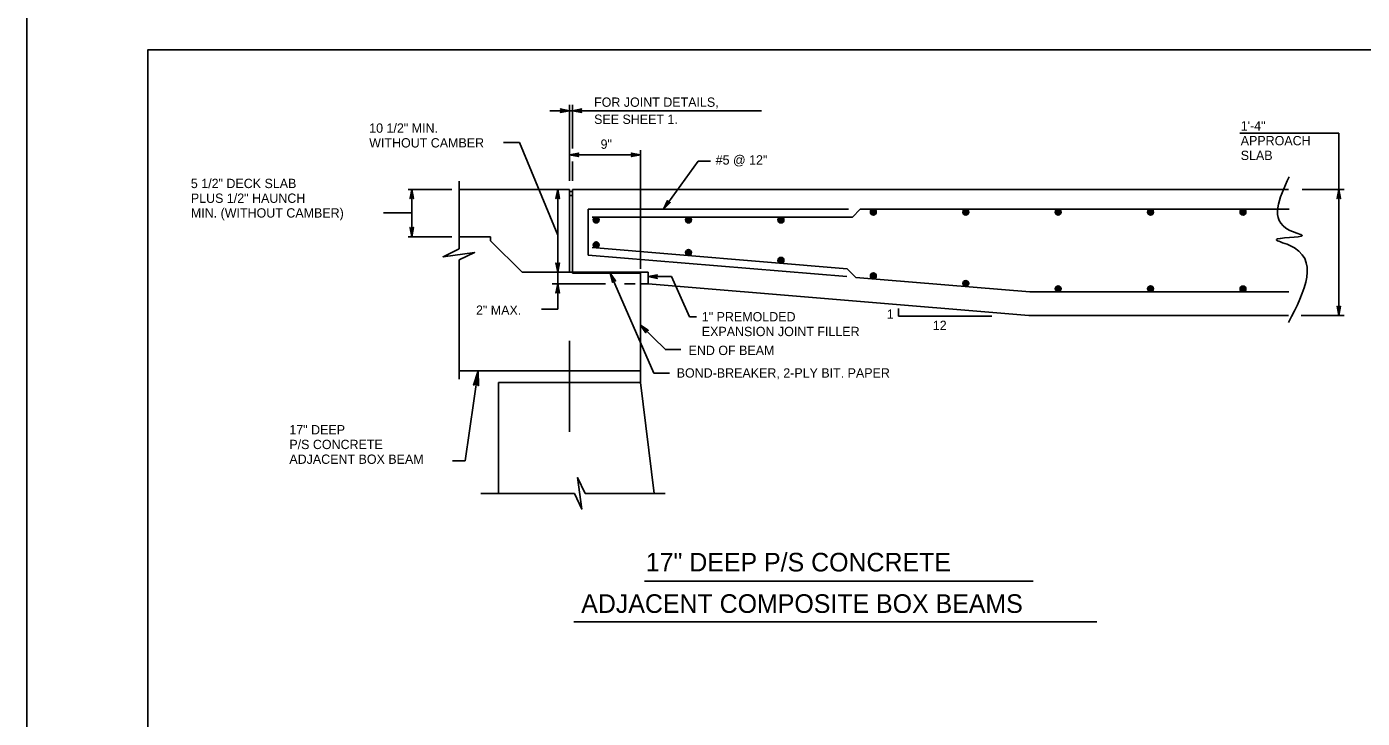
# Model space of a CAD drawing. Extents: x 638079 to 640019, y 297691 to 298879.
# Drawn here: x 638274 to 638704.2, y 298055 to 298277.7 of the extents above; entities that cross this region are included whole.
import ezdxf

# ---------------------------------------------------------------- set-up
doc = ezdxf.new("R2010")
doc.units = 0
doc.layers.add('1', color=7, linetype='Continuous')
doc.layers.add('PLT-BNDY', color=7, linetype='Continuous')

msp = doc.modelspace()

# ---------------------------------------------------------------- linework, layer by layer
at = {"layer": '1'}
for p, q in [((638442.52, 298250.68), (638510.73, 298250.68)), ((638448.85, 298228.12), (638448.85, 298252.54)), ((638449.8, 298238.5), (638449.8, 298252.54)), ((638664.75, 298243.41), (638696.63, 298243.41)), ((638696.63, 298184.69), (638696.63, 298243.41)), ((638471.71, 298236.45), (638448.85, 298236.45)), ((638471.71, 298199.8), (638471.71, 298237.97)), ((638449.8, 298228.12), (638449.8, 298234.3)), ((638490.27, 298234.45), (638479.1, 298218.98)), ((638490.27, 298234.45), (638494.22, 298234.45)), ((638413.31, 298227.96), (638413.31, 298206.16)), ((638396.92, 298225.33), (638410.98, 298225.33)), ((638398.04, 298210.09), (638398.04, 298225.33)), ((638413.31, 298225.33), (638448.85, 298225.33)), ((638447.1, 298225.33), (638443.31, 298225.33)), ((638445.06, 298186.72), (638445.06, 298225.33)), ((638448.85, 298225.33), (638448.85, 298198.66)), ((638448.85, 298223.42), (638449.8, 298223.42)), ((638449.8, 298225.33), (638680.46, 298225.33)), ((638449.8, 298225.33), (638449.8, 298198.66)), ((638684.79, 298225.33), (638698.38, 298225.33)), ((638454.88, 298218.98), (638454.88, 298204.17)), ((638454.88, 298218.98), (638538.7, 298218.98)), ((638539.97, 298216.44), (638542.51, 298218.98)), ((638542.51, 298218.98), (638680.64, 298218.98)), ((638388.91, 298217.81), (638398.04, 298217.81)), ((638456.1, 298216.44), (638539.97, 298216.44)), ((638396.92, 298210.09), (638410.98, 298210.09)), ((638413.31, 298210.09), (638423.44, 298210.09)), ((638423.44, 298208.82), (638423.44, 298210.09)), ((638433.61, 298198.66), (638423.44, 298208.82)), ((638456.1, 298206.62), (638538.33, 298199.76)), ((638413.31, 298202.64), (638413.31, 298164.25)), ((638454.88, 298204.17), (638538.12, 298197.23)), ((638433.61, 298198.66), (638471.71, 298198.66)), ((638449.8, 298198.36), (638449.8, 298198.66)), ((638449.8, 298198.36), (638449.8, 298198.66)), ((638449.8, 298198.36), (638471.71, 298198.36)), ((638453.1, 298198.66), (638467.52, 298198.66)), ((638471.71, 298198.66), (638471.71, 298163.1)), ((638474.21, 298197.23), (638481.68, 298197.23)), ((638481.68, 298197.23), (638487.45, 298184.28)), ((638538.33, 298199.76), (638541.11, 298196.98)), ((638460.48, 298194.91), (638443.31, 298194.91)), ((638469.96, 298194.91), (638466.53, 298194.91)), ((638474.21, 298194.91), (638596.83, 298184.69)), ((638541.11, 298196.98), (638597.15, 298192.31)), ((638597.15, 298192.31), (638680.53, 298192.31)), ((638596.83, 298184.69), (638680.46, 298184.69)), ((638684.47, 298184.69), (638698.38, 298184.69)), ((638489.71, 298184.28), (638487.45, 298184.28)), ((638448.85, 298147.27), (638448.85, 298176.57)), ((638471.71, 298166.91), (638413.31, 298166.91)), ((638415.28, 298137.88), (638419.42, 298166.91)), ((638425.99, 298163.1), (638471.71, 298163.1)), ((638425.99, 298127.36), (638425.99, 298163.1)), ((638476.17, 298127.36), (638471.71, 298163.1)), ((638411.14, 298137.88), (638415.28, 298137.88)), ((638450.42, 298127.36), (638420.24, 298127.36)), ((638479.61, 298127.36), (638453.94, 298127.36)), ((638473.01, 298099.18), (638598.21, 298099.18)), ((638450.27, 298086.05), (638618.7, 298086.05))]:
    msp.add_line(p, q, dxfattribs=at)
for points in [[(639099.03, 297706.23), (639099.03, 298270.23), (638313.03, 298270.23), (638313.03, 297706.23), (639099.03, 297706.23), (639099.03, 297732.59), (638899.03, 297732.59), (638899.03, 297797.26), (639099.03, 297797.26), (639099.03, 297826.23), (638899.03, 297826.23), (638899.03, 297706.23), (638977.83, 297706.23), (638977.83, 297732.59), (638977.83, 297706.23), (639054.83, 297706.23), (639054.83, 297732.59), (639054.83, 297720.27), (639099.03, 297720.27)], [(638448.85, 298250.68), (638445.86, 298250.12), (638445.98, 298250.2), (638446.09, 298250.28), (638446.15, 298250.38), (638446.21, 298250.48), (638446.23, 298250.58), (638446.25, 298250.68), (638446.23, 298250.78), (638446.21, 298250.88), (638446.15, 298250.98), (638446.09, 298251.08), (638445.98, 298251.16), (638445.86, 298251.24), (638448.85, 298250.68), (638445.98, 298251.16), (638446.09, 298251.08), (638448.85, 298250.68), (638446.15, 298250.98), (638446.21, 298250.88), (638448.85, 298250.68), (638446.23, 298250.78), (638446.25, 298250.68), (638448.85, 298250.68), (638446.23, 298250.58), (638446.21, 298250.48), (638448.85, 298250.68), (638446.15, 298250.38), (638446.09, 298250.28), (638448.85, 298250.68), (638445.98, 298250.2)], [(638449.8, 298250.68), (638452.78, 298251.24), (638452.67, 298251.16), (638452.55, 298251.08), (638452.49, 298250.98), (638452.43, 298250.88), (638452.42, 298250.78), (638452.4, 298250.68), (638452.42, 298250.58), (638452.43, 298250.48), (638452.49, 298250.38), (638452.55, 298250.28), (638452.67, 298250.2), (638452.78, 298250.12), (638449.8, 298250.68), (638452.67, 298250.2), (638452.55, 298250.28), (638449.8, 298250.68), (638452.49, 298250.38), (638452.43, 298250.48), (638449.8, 298250.68), (638452.42, 298250.58), (638452.4, 298250.68), (638449.8, 298250.68), (638452.42, 298250.78), (638452.43, 298250.88), (638449.8, 298250.68), (638452.49, 298250.98), (638452.55, 298251.08), (638449.8, 298250.68), (638452.67, 298251.16)], [(638427.63, 298240.47), (638432.72, 298240.47), (638445.06, 298210.63)], [(638448.85, 298236.45), (638451.83, 298237.01), (638451.71, 298236.93), (638451.6, 298236.85), (638451.54, 298236.75), (638451.48, 298236.65), (638451.46, 298236.55), (638451.45, 298236.45), (638451.46, 298236.35), (638451.48, 298236.25), (638451.54, 298236.15), (638451.6, 298236.05), (638451.71, 298235.98), (638451.83, 298235.9), (638448.85, 298236.45), (638451.71, 298235.98), (638451.6, 298236.05), (638448.85, 298236.45), (638451.54, 298236.15), (638451.48, 298236.25), (638448.85, 298236.45), (638451.46, 298236.35), (638451.45, 298236.45), (638448.85, 298236.45), (638451.46, 298236.55), (638451.48, 298236.65), (638448.85, 298236.45), (638451.54, 298236.75), (638451.6, 298236.85), (638448.85, 298236.45), (638451.71, 298236.93)], [(638471.71, 298236.45), (638468.72, 298235.9), (638468.84, 298235.98), (638468.95, 298236.05), (638469.01, 298236.15), (638469.07, 298236.25), (638469.09, 298236.35), (638469.11, 298236.45), (638469.09, 298236.55), (638469.07, 298236.65), (638469.01, 298236.75), (638468.95, 298236.85), (638468.84, 298236.93), (638468.72, 298237.01), (638471.71, 298236.45), (638468.84, 298236.93), (638468.95, 298236.85), (638471.71, 298236.45), (638469.01, 298236.75), (638469.07, 298236.65), (638471.71, 298236.45), (638469.09, 298236.55), (638469.11, 298236.45), (638471.71, 298236.45), (638469.09, 298236.35), (638469.07, 298236.25), (638471.71, 298236.45), (638469.01, 298236.15), (638468.95, 298236.05), (638471.71, 298236.45), (638468.84, 298235.98)], [(638398.04, 298225.33), (638398.6, 298222.35), (638398.52, 298222.46), (638398.44, 298222.58), (638398.34, 298222.64), (638398.24, 298222.7), (638398.14, 298222.72), (638398.04, 298222.73), (638397.94, 298222.72), (638397.84, 298222.7), (638397.74, 298222.64), (638397.64, 298222.58), (638397.56, 298222.46), (638397.48, 298222.35), (638398.04, 298225.33), (638397.56, 298222.46), (638397.64, 298222.58), (638398.04, 298225.33), (638397.74, 298222.64), (638397.84, 298222.7), (638398.04, 298225.33), (638397.94, 298222.72), (638398.04, 298222.73), (638398.04, 298225.33), (638398.14, 298222.72), (638398.24, 298222.7), (638398.04, 298225.33), (638398.34, 298222.64), (638398.44, 298222.58), (638398.04, 298225.33), (638398.52, 298222.46)], [(638445.06, 298225.33), (638445.61, 298222.35), (638445.54, 298222.46), (638445.46, 298222.58), (638445.36, 298222.64), (638445.26, 298222.7), (638445.16, 298222.72), (638445.06, 298222.73), (638444.96, 298222.72), (638444.86, 298222.7), (638444.76, 298222.64), (638444.66, 298222.58), (638444.58, 298222.46), (638444.5, 298222.35), (638445.06, 298225.33), (638444.58, 298222.46), (638444.66, 298222.58), (638445.06, 298225.33), (638444.76, 298222.64), (638444.86, 298222.7), (638445.06, 298225.33), (638444.96, 298222.72), (638445.06, 298222.73), (638445.06, 298225.33), (638445.16, 298222.72), (638445.26, 298222.7), (638445.06, 298225.33), (638445.36, 298222.64), (638445.46, 298222.58), (638445.06, 298225.33), (638445.54, 298222.46)], [(638696.63, 298225.33), (638697.19, 298222.35), (638697.11, 298222.46), (638697.03, 298222.58), (638696.93, 298222.64), (638696.83, 298222.7), (638696.73, 298222.72), (638696.63, 298222.73), (638696.53, 298222.72), (638696.43, 298222.7), (638696.33, 298222.64), (638696.23, 298222.58), (638696.15, 298222.46), (638696.07, 298222.35), (638696.63, 298225.33), (638696.15, 298222.46), (638696.23, 298222.58), (638696.63, 298225.33), (638696.33, 298222.64), (638696.43, 298222.7), (638696.63, 298225.33), (638696.53, 298222.72), (638696.63, 298222.73), (638696.63, 298225.33), (638696.73, 298222.72), (638696.83, 298222.7), (638696.63, 298225.33), (638696.93, 298222.64), (638697.03, 298222.58), (638696.63, 298225.33), (638697.11, 298222.46)], [(638479.1, 298218.98), (638480.39, 298221.73), (638480.39, 298221.59), (638480.39, 298221.45), (638480.43, 298221.34), (638480.48, 298221.24), (638480.55, 298221.16), (638480.62, 298221.09), (638480.71, 298221.05), (638480.8, 298221), (638480.92, 298220.99), (638481.04, 298220.98), (638481.17, 298221.03), (638481.3, 298221.07), (638479.1, 298218.98), (638481.17, 298221.03), (638481.04, 298220.98), (638479.1, 298218.98), (638480.92, 298220.99), (638480.8, 298221), (638479.1, 298218.98), (638480.71, 298221.05), (638480.62, 298221.09), (638479.1, 298218.98), (638480.55, 298221.16), (638480.48, 298221.24), (638479.1, 298218.98), (638480.43, 298221.34), (638480.39, 298221.45), (638479.1, 298218.98), (638480.39, 298221.59)], [(638398.04, 298210.09), (638397.48, 298213.08), (638397.56, 298212.96), (638397.64, 298212.85), (638397.74, 298212.79), (638397.84, 298212.73), (638397.94, 298212.71), (638398.04, 298212.69), (638398.14, 298212.71), (638398.24, 298212.73), (638398.34, 298212.79), (638398.44, 298212.85), (638398.52, 298212.96), (638398.6, 298213.08), (638398.04, 298210.09), (638398.52, 298212.96), (638398.44, 298212.85), (638398.04, 298210.09), (638398.34, 298212.79), (638398.24, 298212.73), (638398.04, 298210.09), (638398.14, 298212.71), (638398.04, 298212.69), (638398.04, 298210.09), (638397.94, 298212.71), (638397.84, 298212.73), (638398.04, 298210.09), (638397.74, 298212.79), (638397.64, 298212.85), (638398.04, 298210.09), (638397.56, 298212.96)], [(638413.31, 298206.16), (638408.12, 298203.63), (638418.27, 298205.01), (638413.31, 298202.64)], [(638445.06, 298198.66), (638444.5, 298201.65), (638444.58, 298201.53), (638444.66, 298201.42), (638444.76, 298201.36), (638444.86, 298201.3), (638444.96, 298201.28), (638445.06, 298201.26), (638445.16, 298201.28), (638445.26, 298201.3), (638445.36, 298201.36), (638445.46, 298201.42), (638445.54, 298201.53), (638445.61, 298201.65), (638445.06, 298198.66), (638445.54, 298201.53), (638445.46, 298201.42), (638445.06, 298198.66), (638445.36, 298201.36), (638445.26, 298201.3), (638445.06, 298198.66), (638445.16, 298201.28), (638445.06, 298201.26), (638445.06, 298198.66), (638444.96, 298201.28), (638444.86, 298201.3), (638445.06, 298198.66), (638444.76, 298201.36), (638444.66, 298201.42), (638445.06, 298198.66), (638444.58, 298201.53)], [(638481.03, 298166.19), (638476.03, 298166.19), (638461.98, 298198.36)], [(638461.98, 298198.36), (638463.7, 298195.86), (638463.58, 298195.93), (638463.47, 298196), (638463.35, 298196.02), (638463.23, 298196.03), (638463.14, 298196.01), (638463.04, 298195.98), (638462.95, 298195.93), (638462.87, 298195.87), (638462.8, 298195.77), (638462.73, 298195.68), (638462.71, 298195.54), (638462.68, 298195.4), (638461.98, 298198.36), (638462.71, 298195.54), (638462.73, 298195.68), (638461.98, 298198.36), (638462.8, 298195.77), (638462.87, 298195.87), (638461.98, 298198.36), (638462.95, 298195.93), (638463.04, 298195.98), (638461.98, 298198.36), (638463.14, 298196.01), (638463.23, 298196.03), (638461.98, 298198.36), (638463.35, 298196.02), (638463.47, 298196), (638461.98, 298198.36), (638463.58, 298195.93)], [(638474.21, 298197.23), (638477.19, 298197.79), (638477.07, 298197.71), (638476.96, 298197.63), (638476.9, 298197.53), (638476.84, 298197.43), (638476.82, 298197.33), (638476.81, 298197.23), (638476.82, 298197.13), (638476.84, 298197.03), (638476.9, 298196.93), (638476.96, 298196.83), (638477.07, 298196.75), (638477.19, 298196.67), (638474.21, 298197.23), (638477.07, 298196.75), (638476.96, 298196.83), (638474.21, 298197.23), (638476.9, 298196.93), (638476.84, 298197.03), (638474.21, 298197.23), (638476.82, 298197.13), (638476.81, 298197.23), (638474.21, 298197.23), (638476.82, 298197.33), (638476.84, 298197.43), (638474.21, 298197.23), (638476.9, 298197.53), (638476.96, 298197.63), (638474.21, 298197.23), (638477.07, 298197.71)], [(638445.06, 298194.91), (638445.61, 298191.93), (638445.54, 298192.04), (638445.46, 298192.16), (638445.36, 298192.22), (638445.26, 298192.28), (638445.16, 298192.3), (638445.06, 298192.31), (638444.96, 298192.3), (638444.86, 298192.28), (638444.76, 298192.22), (638444.66, 298192.16), (638444.58, 298192.04), (638444.5, 298191.93), (638445.06, 298194.91), (638444.58, 298192.04), (638444.66, 298192.16), (638445.06, 298194.91), (638444.76, 298192.22), (638444.86, 298192.28), (638445.06, 298194.91), (638444.96, 298192.3), (638445.06, 298192.31), (638445.06, 298194.91), (638445.16, 298192.3), (638445.26, 298192.28), (638445.06, 298194.91), (638445.36, 298192.22), (638445.46, 298192.16), (638445.06, 298194.91), (638445.54, 298192.04)], [(638439.81, 298186.72), (638445.06, 298186.72)], [(638584.84, 298184.51), (638554.84, 298184.51), (638554.84, 298187.01)], [(638696.63, 298184.69), (638696.07, 298187.68), (638696.15, 298187.56), (638696.23, 298187.45), (638696.33, 298187.39), (638696.43, 298187.33), (638696.53, 298187.31), (638696.63, 298187.29), (638696.73, 298187.31), (638696.83, 298187.33), (638696.93, 298187.39), (638697.03, 298187.45), (638697.11, 298187.56), (638697.19, 298187.68), (638696.63, 298184.69), (638697.11, 298187.56), (638697.03, 298187.45), (638696.63, 298184.69), (638696.93, 298187.39), (638696.83, 298187.33), (638696.63, 298184.69), (638696.73, 298187.31), (638696.63, 298187.29), (638696.63, 298184.69), (638696.53, 298187.31), (638696.43, 298187.33), (638696.63, 298184.69), (638696.33, 298187.39), (638696.23, 298187.45), (638696.63, 298184.69), (638696.15, 298187.56)], [(638484.74, 298173.77), (638479.74, 298173.77), (638471.71, 298181.66)], [(638471.71, 298181.66), (638474.22, 298179.97), (638474.09, 298179.99), (638473.95, 298180.01), (638473.84, 298179.98), (638473.72, 298179.96), (638473.64, 298179.9), (638473.56, 298179.84), (638473.5, 298179.75), (638473.44, 298179.67), (638473.42, 298179.56), (638473.39, 298179.44), (638473.42, 298179.31), (638473.44, 298179.17), (638471.71, 298181.66), (638473.42, 298179.31), (638473.39, 298179.44), (638471.71, 298181.66), (638473.42, 298179.56), (638473.44, 298179.67), (638471.71, 298181.66), (638473.5, 298179.75), (638473.56, 298179.84), (638471.71, 298181.66), (638473.64, 298179.9), (638473.72, 298179.96), (638471.71, 298181.66), (638473.84, 298179.98), (638473.95, 298180.01), (638471.71, 298181.66), (638474.09, 298179.99)], [(638418.21, 298162.5), (638418.56, 298162.62), (638419.42, 298166.91), (638418.21, 298162.5), (638417.98, 298162.29), (638419.42, 298166.91), (638419.02, 298162.56), (638419.32, 298162.35), (638419.42, 298166.91), (638419.5, 298162.08), (638419.32, 298162.35)], [(638453.94, 298127.36), (638451.4, 298132.54), (638452.78, 298122.39), (638450.42, 298127.36)]]:
    msp.add_lwpolyline(points, dxfattribs=at)
for points in [[(638448.85, 298223.42), (638449.8, 298223.42), (638449.8, 298224.7), (638448.85, 298224.7)], [(638448.85, 298198.66), (638449.8, 298198.66), (638449.8, 298223.42), (638448.85, 298223.42)], [(638474.21, 298198.66), (638474.21, 298194.91), (638471.71, 298194.91), (638471.71, 298198.66)]]:
    msp.add_lwpolyline(points, close=True, dxfattribs=at)
for centre, radius in [((638546.71, 298218.03), 0.952), ((638546.71, 298218.03), 0.714), ((638576.47, 298218.03), 0.952), ((638576.47, 298218.03), 0.714), ((638606.24, 298218.03), 0.952), ((638606.24, 298218.03), 0.714), ((638636, 298218.03), 0.952), ((638636, 298218.03), 0.714), ((638665.77, 298218.03), 0.952), ((638665.77, 298218.03), 0.714), ((638457.42, 298215.49), 0.952), ((638457.42, 298215.49), 0.714), ((638457.42, 298215.49), 0.476), ((638457.42, 298215.49), 0.238), ((638487.18, 298215.49), 0.952), ((638487.18, 298215.49), 0.714), ((638487.18, 298215.49), 0.476), ((638487.18, 298215.49), 0.238), ((638516.95, 298215.49), 0.952), ((638516.95, 298215.49), 0.714), ((638516.95, 298215.49), 0.476), ((638516.95, 298215.49), 0.238), ((638546.71, 298218.03), 0.476), ((638546.71, 298218.03), 0.238), ((638576.47, 298218.03), 0.476), ((638576.47, 298218.03), 0.238), ((638606.24, 298218.03), 0.476), ((638606.24, 298218.03), 0.238), ((638636, 298218.03), 0.476), ((638636, 298218.03), 0.238), ((638665.77, 298218.03), 0.476), ((638665.77, 298218.03), 0.238), ((638457.42, 298207.5), 0.952), ((638457.42, 298207.5), 0.714), ((638457.42, 298207.5), 0.476), ((638457.42, 298207.5), 0.238), ((638487.18, 298204.98), 0.952), ((638487.18, 298204.98), 0.714), ((638487.18, 298204.98), 0.476), ((638487.18, 298204.98), 0.238), ((638516.95, 298202.49), 0.952), ((638516.95, 298202.49), 0.714), ((638516.95, 298202.49), 0.476), ((638516.95, 298202.49), 0.238), ((638546.71, 298197.46), 0.952), ((638546.71, 298197.46), 0.714), ((638546.71, 298197.46), 0.476), ((638546.71, 298197.46), 0.238), ((638576.47, 298195.02), 0.952), ((638576.47, 298195.02), 0.714), ((638576.47, 298195.02), 0.476), ((638576.47, 298195.02), 0.238), ((638606.24, 298193.29), 0.952), ((638606.24, 298193.29), 0.714), ((638606.24, 298193.29), 0.476), ((638606.24, 298193.29), 0.238), ((638636, 298193.29), 0.952), ((638636, 298193.29), 0.714), ((638636, 298193.29), 0.476), ((638636, 298193.29), 0.238), ((638665.77, 298193.26), 0.952), ((638665.77, 298193.26), 0.714), ((638665.77, 298193.26), 0.476), ((638665.77, 298193.26), 0.238)]:
    msp.add_circle(centre, radius, dxfattribs=at)
msp.add_spline([(638680.46, 298182.43), (638680.67, 298207.36), (638676.51, 298209.15), (638684.84, 298210.45), (638680.67, 298212.24), (638680.64, 298229.4)], degree=3, dxfattribs=at)
at = {"layer": 'PLT-BNDY'}
msp.add_lwpolyline([(638274.03, 298285.23), (639115.03, 298285.23), (639115.03, 297691.23), (638274.03, 297691.23)], close=True, dxfattribs=at)

# ---------------------------------------------------------------- texts
at = {"layer": '1'}
for s, height, p in [('FOR JOINT DETAILS,', 3, (638456.77, 298251.93)), ('SEE SHEET 1.', 3, (638456.77, 298246.43)), ('10 1/2" MIN.', 3, (638384.34, 298243.58)), ('1\'-4"', 3, (638665.03, 298244.29)), ('WITHOUT CAMBER', 3, (638384.34, 298238.83)), ('9"', 3, (638458.85, 298238.41)), ('APPROACH', 3, (638665.03, 298239.54)), ('#5 @ 12"', 3, (638495.93, 298233.33)), ('SLAB', 3, (638665.03, 298234.79)), ('5 1/2" DECK SLAB', 3, (638326.9, 298225.75)), ('PLUS 1/2" HAUNCH', 3, (638326.9, 298221)), ('MIN. (WITHOUT CAMBER)', 3, (638326.9, 298216.26)), ('2" MAX.', 3, (638418.73, 298184.94)), ('1" PREMOLDED', 3, (638491.46, 298182.83)), ('1', 3, (638551.04, 298183.66)), ('EXPANSION JOINT FILLER', 3, (638491.46, 298178.08)), ('12', 3, (638565.86, 298180.05)), ('END OF BEAM', 3, (638487.2, 298171.99)), ('BOND-BREAKER, 2-PLY BIT. PAPER', 3, (638483.37, 298164.72)), ('17" DEEP', 3, (638358.62, 298146.44)), ('P/S CONCRETE', 3, (638358.62, 298141.7)), ('ADJACENT BOX BEAM', 3, (638358.62, 298136.95)), ('17" DEEP P/S CONCRETE', 6, (638473.43, 298102.29)), ('ADJACENT COMPOSITE BOX BEAMS', 6, (638452.63, 298088.95))]:
    msp.add_text(s, height=height, dxfattribs=at).set_placement(p)

doc.saveas('drawing.dxf')
